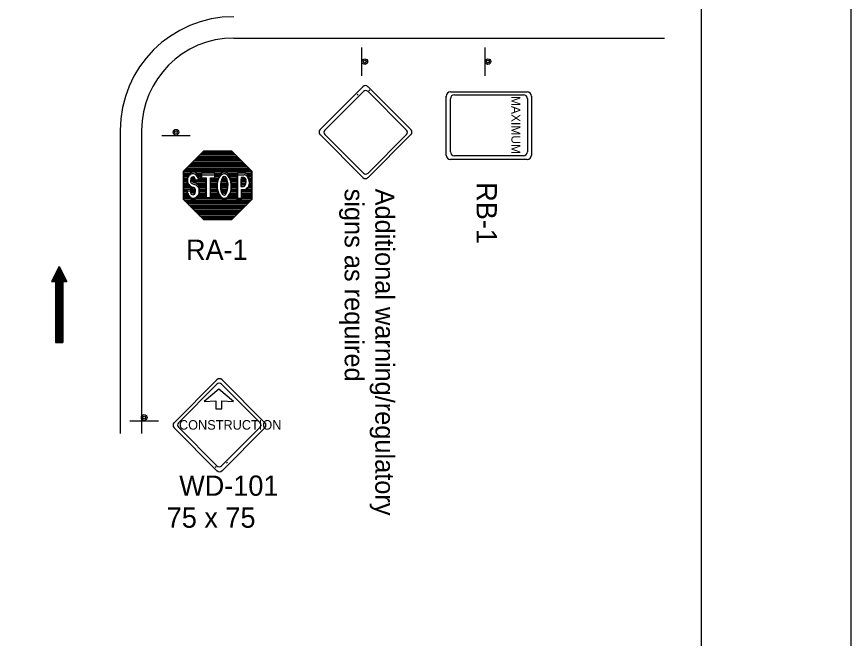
# Model space of a CAD drawing. Extents: x 1833 to 2049, y 205 to 484.
# Drawn here: x 1942.9 to 2049.5, y 284.7 to 364.1 of the extents above; entities that cross this region are included whole.
import ezdxf

# ---------------------------------------------------------------- set-up
doc = ezdxf.new("R2010")
doc.units = 0
for name, color, linetype in [('Level 10', 7, 'Continuous'), ('Level 2', 7, 'Continuous'), ('Level 44', 7, 'Continuous'), ('Level 60', 7, 'Continuous')]:
    doc.layers.add(name, color=color, linetype=linetype)

msp = doc.modelspace()

# ---------------------------------------------------------------- linework, layer by layer
at = {"layer": 'Level 10'}
for p, q in [((1970.6, 361.34), (2025.58, 361.34)), ((1956.08, 349.55), (1956.08, 310.88)), ((1958.81, 349.55), (1958.81, 310.88)), ((1948.28, 332.18), (1947.31, 330.25)), ((1948.04, 331.7), (1948.04, 322.5)), ((1948.16, 331.94), (1948.16, 322.5)), ((1948.28, 332.18), (1948.28, 322.5)), ((1948.28, 332.18), (1949.25, 330.25)), ((1948.4, 331.94), (1948.4, 322.5)), ((1948.52, 331.7), (1948.52, 322.5)), ((1947.43, 330.49), (1947.43, 330.25)), ((1947.56, 330.73), (1947.56, 330.25)), ((1947.68, 330.97), (1947.68, 330.25)), ((1947.8, 331.22), (1947.8, 322.5)), ((1947.92, 331.46), (1947.92, 322.5)), ((1948.64, 331.46), (1948.64, 322.5)), ((1948.76, 331.22), (1948.76, 322.5)), ((1948.89, 330.97), (1948.89, 330.25)), ((1949.01, 330.73), (1949.01, 330.25)), ((1949.13, 330.49), (1949.13, 330.25)), ((1947.31, 330.25), (1947.8, 330.25)), ((1947.8, 330.25), (1947.8, 322.5)), ((1948.76, 330.25), (1948.76, 322.5)), ((1948.76, 330.25), (1949.25, 330.25)), ((1947.8, 322.5), (1948.76, 322.5))]:
    msp.add_line(p, q, dxfattribs=at)
for radius in [14.52, 11.79]:
    msp.add_arc((1970.6, 349.55), radius, 90, 180, dxfattribs=at)
at = {"layer": 'Level 2'}
for p, q in [((1986.39, 354.06), (1986.49, 354.17)), ((1987.84, 354.63), (1987.95, 354.73)), ((1969.77, 307.2), (1969.67, 307.09)), ((1968.32, 306.63), (1968.22, 306.53))]:
    msp.add_line(p, q, dxfattribs=at)
at = {"layer": 'Level 44'}
for p, q in [((1986.91, 360.15), (1986.91, 356.52)), ((2002.64, 360.15), (2002.64, 356.52)), ((1987.08, 355.13), (1981.61, 349.66)), ((1993.21, 349.66), (1987.73, 355.13)), ((1982.22, 349.6), (1987.14, 354.53)), ((1987.73, 354.53), (1992.66, 349.6)), ((1998.28, 354.48), (2008.06, 354.48)), ((1998.28, 354.48), (1998.28, 354.48)), ((1998.77, 354.1), (1998.78, 354.1)), ((1998.78, 354.1), (2007.57, 354.1)), ((1997.7, 346.41), (1997.7, 353.91)), ((1997.94, 353.77), (1997.94, 353.77)), ((1998.25, 346.83), (1998.25, 353.58)), ((2008.1, 353.58), (2008.1, 346.83)), ((2008.63, 353.91), (2008.63, 346.41)), ((1961.38, 348.91), (1965.01, 348.91)), ((1981.61, 349.01), (1987.08, 343.54)), ((1987.14, 344.09), (1982.22, 349.01)), ((1987.73, 343.54), (1993.21, 349.01)), ((1992.66, 349.01), (1987.73, 344.09)), ((1993.2, 349.66), (1993.21, 349.66)), ((2006.32, 349.33), (2006.32, 349.33)), ((1966.7, 346.9), (1964.15, 344.36)), ((1970.33, 346.9), (1966.7, 346.9)), ((1972.88, 344.36), (1970.33, 346.9)), ((2008.06, 345.83), (1998.28, 345.83)), ((2007.57, 346.31), (1998.78, 346.31)), ((1964.15, 344.36), (1964.15, 340.73)), ((1972.88, 340.73), (1972.88, 344.36)), ((1966.41, 343.31), (1966.41, 343.87)), ((1966.41, 343.87), (1968.11, 343.87)), ((1967, 343.31), (1966.41, 343.31)), ((1966.46, 344.08), (1966.46, 343.52)), ((1968.15, 344.08), (1966.46, 344.08)), ((1966.46, 343.52), (1967.04, 343.52)), ((1967, 340.8), (1967, 343.31)), ((1967.04, 343.52), (1967.04, 341.01)), ((1968.11, 343.3), (1967.55, 343.3)), ((1967.55, 343.3), (1967.55, 340.8)), ((1967.6, 341.01), (1967.6, 343.51)), ((1967.6, 343.51), (1968.15, 343.51)), ((1968.11, 343.87), (1968.11, 343.3)), ((1968.15, 343.51), (1968.15, 344.08)), ((1969.29, 343.47), (1969.31, 343.47)), ((1969.31, 344.01), (1969.32, 344.01)), ((1971, 340.7), (1971, 343.9)), ((1971, 343.9), (1971.9, 343.9)), ((1971.94, 344.11), (1971.05, 344.11)), ((1971.05, 344.11), (1971.05, 340.91)), ((1971.47, 343.32), (1971.47, 342.39)), ((1971.82, 343.32), (1971.47, 343.32)), ((1971.82, 343.32), (1971.47, 343.32)), ((1971.47, 343.32), (1971.47, 342.39)), ((1971.86, 343.53), (1971.51, 343.53)), ((1971.51, 343.53), (1971.51, 342.61)), ((1971.51, 343.53), (1971.51, 342.61)), ((1971.86, 343.53), (1971.51, 343.53)), ((1966.15, 342.98), (1965.6, 342.98)), ((1966.19, 343.19), (1965.65, 343.19)), ((1971.47, 342.39), (1971.81, 342.39)), ((1971.47, 342.39), (1971.81, 342.39)), ((1971.51, 342.61), (1971.86, 342.61)), ((1971.51, 342.61), (1971.86, 342.61)), ((1964.53, 341.83), (1965.03, 341.83)), ((1964.58, 342.04), (1965.08, 342.04)), ((1964.69, 341.2), (1964.69, 341.2)), ((1971.85, 341.8), (1971.53, 341.79)), ((1971.53, 341.79), (1971.87, 341.79)), ((1971.53, 341.79), (1971.53, 340.7)), ((1971.58, 340.91), (1971.58, 342)), ((1971.58, 342), (1971.91, 342)), ((1964.15, 340.73), (1966.7, 338.18)), ((1967.55, 340.8), (1967, 340.8)), ((1967.04, 341.01), (1967.6, 341.01)), ((1970.33, 338.18), (1972.88, 340.73)), ((1971.53, 340.7), (1971, 340.7)), ((1971.05, 340.91), (1971.58, 340.91)), ((1966.7, 338.18), (1970.33, 338.18)), ((1968.43, 317.72), (1962.95, 312.25)), ((1974.55, 312.25), (1969.08, 317.72)), ((1963.5, 312.25), (1968.43, 317.17)), ((1969.02, 317.17), (1973.94, 312.25)), ((1968.68, 316.53), (1966.79, 314.94)), ((1970.56, 314.94), (1968.68, 316.53)), ((1966.79, 314.94), (1968.3, 315.02)), ((1968.3, 315.02), (1968.3, 314.01)), ((1969.05, 314.01), (1969.05, 315.02)), ((1969.05, 315.02), (1970.56, 314.94)), ((1968.3, 314.01), (1969.05, 314.01)), ((1957.32, 312.5), (1960.95, 312.5)), ((1962.95, 311.6), (1968.43, 306.12)), ((1962.96, 311.6), (1962.95, 311.6)), ((1968.43, 306.74), (1963.5, 311.66)), ((1973.94, 311.66), (1969.02, 306.74)), ((1969.08, 306.12), (1974.55, 311.6))]:
    msp.add_line(p, q, dxfattribs=at)
msp.add_lwpolyline([(1972.88, 340.73), (1970.33, 338.18), (1966.7, 338.18), (1964.15, 340.73), (1964.15, 344.36), (1966.7, 346.9), (1970.33, 346.9), (1972.88, 344.36)], close=True, dxfattribs=at)
for points in [[(1966.4, 346.61), (1970.62, 346.61)], [(1966.59, 346.79), (1970.45, 346.79)], [(1965.32, 345.52), (1971.72, 345.52)], [(1965.5, 345.7), (1971.54, 345.7)], [(1965.68, 345.88), (1971.35, 345.88)], [(1965.86, 346.06), (1971.17, 346.06)], [(1966.04, 346.24), (1970.99, 346.24)], [(1966.22, 346.42), (1970.81, 346.42)], [(1964.23, 344.43), (1972.81, 344.43)], [(1964.41, 344.61), (1972.62, 344.61)], [(1964.59, 344.79), (1972.44, 344.79)], [(1964.77, 344.97), (1972.26, 344.97)], [(1964.95, 345.15), (1972.08, 345.15)], [(1965.13, 345.33), (1971.9, 345.33)], [(1964.15, 344.25), (1972.88, 344.25)], [(1964.15, 344.06), (1965, 344.06)], [(1964.15, 343.88), (1964.84, 343.88)], [(1964.15, 343.7), (1964.74, 343.7)], [(1964.15, 343.52), (1964.69, 343.52)], [(1964.15, 343.34), (1964.66, 343.34)], [(1965.09, 343.34), (1965.66, 343.34)], [(1965.17, 343.52), (1965.58, 343.52)], [(1965.83, 344.06), (1966.46, 344.06)], [(1965.99, 343.88), (1966.46, 343.88)], [(1966.09, 343.7), (1966.46, 343.7)], [(1966.14, 343.52), (1966.46, 343.52)], [(1966.19, 343.34), (1967.04, 343.34)], [(1967.6, 343.34), (1968.56, 343.34)], [(1968.15, 344.06), (1969, 344.06)], [(1968.15, 343.88), (1968.83, 343.88)], [(1968.15, 343.7), (1968.71, 343.7)], [(1968.15, 343.52), (1968.62, 343.52)], [(1969.03, 343.34), (1969.71, 343.34)], [(1969.12, 343.52), (1969.63, 343.52)], [(1969.77, 344.06), (1971.05, 344.06)], [(1969.94, 343.88), (1971.05, 343.88)], [(1970.06, 343.7), (1971.05, 343.7)], [(1970.13, 343.52), (1971.05, 343.52)], [(1970.2, 343.34), (1971.05, 343.34)], [(1971.51, 343.52), (1971.93, 343.52)], [(1971.51, 343.34), (1972.11, 343.34)], [(1972.11, 344.06), (1972.88, 344.06)], [(1972.34, 343.88), (1972.88, 343.88)], [(1972.46, 343.7), (1972.88, 343.7)], [(1972.55, 343.52), (1972.88, 343.52)], [(1972.59, 343.34), (1972.88, 343.34)], [(1964.15, 343.16), (1964.65, 343.16)], [(1964.15, 342.98), (1964.67, 342.98)], [(1964.15, 342.79), (1964.72, 342.79)], [(1964.15, 342.61), (1964.84, 342.61)], [(1964.15, 342.43), (1965.07, 342.43)], [(1964.15, 342.25), (1965.5, 342.25)], [(1965.12, 343.16), (1967.04, 343.16)], [(1965.35, 342.98), (1967.04, 342.98)], [(1965.76, 342.79), (1967.04, 342.79)], [(1966.01, 342.61), (1967.04, 342.61)], [(1966.14, 342.43), (1967.04, 342.43)], [(1966.19, 342.25), (1967.04, 342.25)], [(1967.6, 343.16), (1968.52, 343.16)], [(1967.6, 342.98), (1968.49, 342.98)], [(1967.6, 342.79), (1968.47, 342.79)], [(1967.6, 342.61), (1968.46, 342.61)], [(1967.6, 342.43), (1968.46, 342.43)], [(1967.6, 342.25), (1968.47, 342.25)], [(1968.91, 342.61), (1969.85, 342.61)], [(1968.91, 342.43), (1969.85, 342.43)], [(1968.92, 342.79), (1969.85, 342.79)], [(1968.93, 342.98), (1969.82, 342.98)], [(1968.93, 342.25), (1969.83, 342.25)], [(1968.98, 343.16), (1969.77, 343.16)], [(1970.24, 343.16), (1971.05, 343.16)], [(1970.28, 342.98), (1971.05, 342.98)], [(1970.29, 342.25), (1971.05, 342.25)], [(1970.3, 342.79), (1971.05, 342.79)], [(1970.3, 342.43), (1971.05, 342.43)], [(1970.31, 342.61), (1971.05, 342.61)], [(1971.51, 343.16), (1972.15, 343.16)], [(1971.51, 342.98), (1972.16, 342.98)], [(1971.51, 342.79), (1972.1, 342.79)], [(1972.36, 342.25), (1972.88, 342.25)], [(1972.48, 342.43), (1972.88, 342.43)], [(1972.55, 342.61), (1972.88, 342.61)], [(1972.6, 342.79), (1972.88, 342.79)], [(1972.61, 343.16), (1972.88, 343.16)], [(1972.62, 342.98), (1972.88, 342.98)], [(1964.15, 342.07), (1965.69, 342.07)], [(1964.15, 341.89), (1964.6, 341.89)], [(1964.15, 341.7), (1964.63, 341.7)], [(1964.15, 341.52), (1964.69, 341.52)], [(1964.15, 341.34), (1964.78, 341.34)], [(1964.15, 341.16), (1964.92, 341.16)], [(1965.09, 341.89), (1965.71, 341.89)], [(1965.15, 341.7), (1965.66, 341.7)], [(1965.93, 341.16), (1967.04, 341.16)], [(1966.06, 341.34), (1967.04, 341.34)], [(1966.15, 341.52), (1967.04, 341.52)], [(1966.21, 341.7), (1967.04, 341.7)], [(1966.22, 342.07), (1967.04, 342.07)], [(1966.22, 341.89), (1967.04, 341.89)], [(1967.6, 342.07), (1968.5, 342.07)], [(1967.6, 341.89), (1968.52, 341.89)], [(1967.6, 341.7), (1968.58, 341.7)], [(1967.6, 341.52), (1968.64, 341.52)], [(1967.6, 341.34), (1968.73, 341.34)], [(1967.6, 341.16), (1968.87, 341.16)], [(1968.97, 342.07), (1969.8, 342.07)], [(1969.03, 341.89), (1969.74, 341.89)], [(1969.1, 341.7), (1969.65, 341.7)], [(1969.87, 341.16), (1971.05, 341.16)], [(1970.01, 341.34), (1971.05, 341.34)], [(1970.1, 341.52), (1971.05, 341.52)], [(1970.17, 341.7), (1971.05, 341.7)], [(1970.22, 341.89), (1971.05, 341.89)], [(1970.26, 342.07), (1971.05, 342.07)], [(1971.58, 341.89), (1972.88, 341.89)], [(1971.58, 341.7), (1972.88, 341.7)], [(1971.58, 341.52), (1972.88, 341.52)], [(1971.58, 341.34), (1972.88, 341.34)], [(1971.58, 341.16), (1972.88, 341.16)], [(1972.11, 342.07), (1972.88, 342.07)], [(1964.15, 340.98), (1965.13, 340.98)], [(1964.15, 340.8), (1972.88, 340.8)], [(1964.26, 340.62), (1972.77, 340.62)], [(1964.44, 340.44), (1972.59, 340.44)], [(1964.63, 340.25), (1972.41, 340.25)], [(1965.69, 340.98), (1969.08, 340.98)], [(1969.66, 340.98), (1971.05, 340.98)], [(1971.58, 340.98), (1972.88, 340.98)], [(1964.81, 340.07), (1972.23, 340.07)], [(1964.99, 339.89), (1972.04, 339.89)], [(1965.17, 339.71), (1971.86, 339.71)], [(1965.35, 339.53), (1971.68, 339.53)], [(1965.53, 339.35), (1971.5, 339.35)], [(1965.72, 339.17), (1971.32, 339.17)], [(1965.9, 338.98), (1971.14, 338.98)], [(1966.08, 338.8), (1970.96, 338.8)], [(1966.26, 338.62), (1970.77, 338.62)], [(1966.45, 338.44), (1970.59, 338.44)], [(1966.62, 338.26), (1970.41, 338.26)]]:
    msp.add_lwpolyline(points, dxfattribs=at)
for centre, radius in [((1987.32, 358.33), 0.363), ((1987.32, 358.33), 0.181), ((2003.05, 358.33), 0.363), ((2003.05, 358.33), 0.181), ((1963.2, 349.32), 0.363), ((1963.2, 349.32), 0.181), ((1959.14, 312.91), 0.363), ((1959.14, 312.91), 0.181)]:
    msp.add_circle(centre, radius, dxfattribs=at)
for centre, radius, start, end in [((1987.4, 354.81), 0.458, 45, 135), ((1987.44, 354.23), 0.412, 45, 135), ((1998.28, 353.9), 0.579, 90, 180), ((1998.77, 353.58), 0.521, 90, 180), ((2007.57, 353.58), 0.521, 360, 90), ((2008.05, 353.9), 0.579, 360, 90), ((1981.93, 349.33), 0.458, 135, 225), ((1982.51, 349.31), 0.412, 135, 225), ((1992.36, 349.31), 0.412, 315, 45), ((1992.88, 349.33), 0.458, 315, 45), ((1998.77, 346.83), 0.521, 180, 270), ((2007.57, 346.83), 0.521, 270, 360), ((1998.28, 346.41), 0.579, 180, 270), ((2008.05, 346.41), 0.579, 270, 360), ((1965.96, 343.01), 1.35, 157.7332, 177.1392), ((1966, 343.22), 1.35, 157.7332, 177.1392), ((1965.84, 343.19), 1.19, 174.8171, 195.9183), ((1965.59, 343.13), 0.967, 123.3662, 155.6734), ((1965.63, 343.34), 0.967, 123.3662, 155.6734), ((1965.34, 343.12), 0.294, 113.8064, 172.2407), ((1965.37, 343.43), 0.591, 46.1369, 121.3987), ((1965.35, 343.29), 0.268, 164.131, 238.1476), ((1965.38, 343.33), 0.294, 113.8064, 172.2407), ((1965.41, 343.64), 0.591, 46.1369, 121.3987), ((1965.31, 343.1), 0.308, 47.3017, 109.0119), ((1965.36, 343.31), 0.308, 47.3017, 109.0119), ((1965.17, 343.04), 0.449, 350.4412, 39.3244), ((1965.22, 343.25), 0.449, 350.4412, 39.3244), ((1965.12, 343.11), 0.998, 14.564, 49.0063), ((1965.16, 343.32), 0.998, 14.564, 49.0063), ((1964.77, 342.95), 1.38, 0.6952, 17.1452), ((1964.81, 343.16), 1.38, 0.6952, 17.1452), ((1971.76, 343.02), 0.315, 35.1198, 79.3117), ((1971.76, 343.02), 0.315, 35.1198, 79.3117), ((1971.81, 343.23), 0.315, 35.1198, 79.3117), ((1971.81, 343.23), 0.315, 35.1198, 79.3117), ((1971.85, 343.37), 0.53, 44.8528, 85.0441), ((1971.9, 343.58), 0.53, 44.8528, 85.0441), ((1971.66, 343.14), 0.489, 8.6031, 34.217), ((1971.66, 343.14), 0.489, 8.6031, 34.217), ((1971.68, 343.14), 0.814, 29.2241, 48.5308), ((1971.68, 343.14), 0.814, 29.2241, 48.5308), ((1971.73, 343.35), 0.814, 29.2241, 48.5308), ((1971.73, 343.35), 0.814, 29.2241, 48.5308), ((1971.67, 343.06), 0.864, 13.0674, 33.762), ((1971.72, 343.27), 0.864, 13.0674, 33.762), ((1970.94, 343.02), 1.68, 3.3903, 15.6597), ((1987.4, 343.86), 0.458, 225, 315), ((1987.44, 344.38), 0.412, 225, 315), ((1965.79, 342.97), 1.19, 174.8171, 195.9183), ((1965.44, 342.94), 0.847, 200.4481, 235.1107), ((1965.49, 343.15), 0.847, 200.4481, 235.1107), ((1967.61, 347.78), 6.13, 244.4624, 248.8312), ((1967.66, 347.99), 6.13, 244.4624, 248.8312), ((1965.3, 343.08), 0.268, 164.131, 238.1476), ((1966.15, 344.43), 1.87, 237.9816, 250.979), ((1966.2, 344.64), 1.87, 237.9816, 250.979), ((1965.34, 341.89), 0.387, 34.2083, 74.1552), ((1965.06, 341.46), 1.31, 46.2465, 67.9263), ((1965.1, 341.67), 1.31, 46.2465, 67.9263), ((1967.72, 343.84), 2.28, 219.479, 223.4261), ((1967.77, 344.06), 2.28, 219.479, 223.4261), ((1964.82, 341.75), 1.36, 5.9097, 21.9865), ((1964.86, 341.96), 1.36, 5.9097, 21.9865), ((1971.74, 342.75), 0.361, 281.9191, 325.7868), ((1971.74, 342.75), 0.361, 281.9191, 325.7868), ((1971.78, 342.96), 0.361, 281.9191, 325.7868), ((1971.78, 342.96), 0.361, 281.9191, 325.7868), ((1971.62, 342.93), 0.489, 8.6031, 34.217), ((1971.62, 342.93), 0.489, 8.6031, 34.217), ((1971.65, 342.8), 0.464, 326.5086, 357.0313), ((1971.65, 342.8), 0.464, 326.5086, 357.0313), ((1971.69, 343.01), 0.464, 326.5086, 357.0313), ((1971.69, 343.01), 0.464, 326.5086, 357.0313), ((1971.6, 342.86), 0.52, 350.3417, 15.2342), ((1971.6, 342.86), 0.52, 350.3417, 15.2342), ((1971.64, 343.08), 0.52, 350.3417, 15.2342), ((1971.64, 343.08), 0.52, 350.3417, 15.2342), ((1971.93, 342.57), 0.531, 295.3838, 322.6188), ((1971.66, 342.61), 0.86, 318.2922, 338.6031), ((1971.66, 342.61), 0.86, 318.2922, 338.6031), ((1971.71, 342.82), 0.86, 318.2922, 338.6031), ((1971.71, 342.82), 0.86, 318.2922, 338.6031), ((1970.82, 342.94), 1.76, 338.3153, 348.6699), ((1970.9, 342.8), 1.68, 3.3903, 15.6597), ((1970.87, 343.15), 1.76, 338.3153, 348.6699), ((1971.23, 342.84), 1.35, 349.7521, 2.7916), ((1971.23, 342.84), 1.35, 349.7521, 2.7916), ((1971.27, 343.05), 1.35, 349.7521, 2.7916), ((1971.27, 343.05), 1.35, 349.7521, 2.7916), ((1966.2, 341.9), 1.67, 182.3841, 204.9519), ((1966.25, 342.11), 1.67, 182.3841, 204.9519), ((1965.74, 341.76), 1.19, 208.4154, 233.6553), ((1965.78, 341.97), 1.19, 208.4154, 233.6553), ((1965.79, 341.82), 0.761, 179.0172, 193.5172), ((1965.43, 341.68), 0.382, 186.8728, 222.7449), ((1965.83, 342.03), 0.761, 179.0172, 193.5172), ((1965.47, 341.89), 0.382, 186.8728, 222.7449), ((1965.38, 341.71), 0.372, 230.6966, 271.4573), ((1965.42, 341.92), 0.372, 230.6966, 271.4573), ((1965.35, 341.68), 0.345, 275.4374, 314.0625), ((1965.3, 341.68), 0.387, 34.2083, 74.1552), ((1965.4, 341.89), 0.345, 275.4374, 314.0625), ((1965.2, 341.68), 0.459, 326.253, 358.7323), ((1965.31, 341.72), 0.355, 352.5761, 30.4776), ((1965.28, 341.74), 0.868, 293.1413, 324.9906), ((1965.25, 341.89), 0.459, 326.253, 358.7323), ((1965.35, 341.93), 0.355, 352.5761, 30.4776), ((1964.7, 341.89), 1.51, 325.5092, 343.2894), ((1964.75, 342.1), 1.51, 325.5092, 343.2894), ((1964.25, 341.75), 1.92, 351.247, 3.9864), ((1964.3, 341.96), 1.92, 351.247, 3.9864), ((1971.88, 341.98), 0.184, 259.7909, 293.5419), ((1971.93, 342.19), 0.184, 259.7909, 293.5419), ((1971.73, 342.56), 0.784, 286.602, 299.8091), ((1971.77, 342.77), 0.784, 286.602, 299.8091), ((1971.89, 342.36), 0.531, 295.3838, 322.6188), ((1965.37, 341.23), 0.544, 232.0536, 292.7397), ((1965.41, 341.44), 0.544, 232.0536, 292.7397), ((1965.24, 341.53), 0.868, 293.1413, 324.9906), ((1968.76, 317.4), 0.458, 45, 135), ((1968.72, 316.88), 0.412, 45, 135), ((1963.28, 311.93), 0.458, 135, 225), ((1963.8, 311.95), 0.412, 135, 225), ((1973.65, 311.95), 0.412, 315, 45), ((1974.23, 311.93), 0.458, 315, 45), ((1968.72, 307.03), 0.412, 225, 315), ((1968.76, 306.45), 0.458, 225, 315)]:
    msp.add_arc(centre, radius, start, end, dxfattribs=at)
for centre, major_axis, ratio, start_param, end_param in [((1969.38, 342.56), (-0.01, -1.66), 0.558644, 3.185857, 9.451311), ((1969.34, 342.35), (-0.01, -1.66), 0.558644, 3.185857, 4.129398), ((1969.38, 342.6), (0.01, -1.09), 0.432619, 3.239639, 9.473919), ((1969.34, 342.39), (0.01, -1.09), 0.432619, 3.239639, 3.888884), ((1969.34, 342.39), (0.01, -1.09), 0.432619, 0.881967, 3.190734), ((1969.34, 342.35), (-0.01, -1.66), 0.558644, 0.656861, 3.168126), ((1969.34, 342.35), (-0.01, -1.66), 0.558644, 4.129576, 6.939747), ((1969.34, 342.39), (0.01, -1.09), 0.432619, 3.890436, 7.165085)]:
    msp.add_ellipse(centre, major_axis=major_axis, ratio=ratio, start_param=start_param, end_param=end_param, dxfattribs=at)
at = {"layer": 'Level 60'}
for points in [[(2049.46, 484.39), (1833.46, 484.39), (1833.46, 205.39), (2049.46, 205.39)], [(2030.33, 473.58), (1843.46, 473.58), (1843.46, 216.2), (2030.33, 216.2)]]:
    msp.add_lwpolyline(points, close=True, dxfattribs=at)

# ---------------------------------------------------------------- texts
at = {"layer": 'Level 10'}
for s, height, p in [('RB-1', 2.585, (2001.6, 342.94)), ('signs as required', 2.419, (1984.75, 342.12)), ('Additional warning/regulatory', 2.419, (1988.66, 342.12))]:
    msp.add_text(s, height=height, rotation=270, dxfattribs=at).set_placement(p)
for s, p in [('RA-1', (1964.48, 333.03)), ('WD-101', (1963.61, 302.92)), ('75 x 75', (1962.02, 298.84))]:
    msp.add_text(s, height=2.585, dxfattribs=at).set_placement(p)
at = {"layer": 'Level 44'}
for s, height, rotation, p in [('MAXIMUM', 1.147, 270, (2006.04, 353.95)), ('CONSTRUCTION', 1.2148, 360, (1963.58, 311.36))]:
    msp.add_text(s, height=height, rotation=rotation, dxfattribs=at).set_placement(p)

doc.saveas('drawing.dxf')
